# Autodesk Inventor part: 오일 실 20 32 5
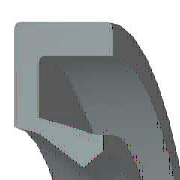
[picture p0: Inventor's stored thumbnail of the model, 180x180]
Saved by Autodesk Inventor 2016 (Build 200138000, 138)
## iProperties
IsCustomPart: 0
Created: 2012-02
Part Number: 오일 실 20 32 5
Material: 고무
Description: 오일 실 - 비스프링, 조립 GA
Document SubType Name: Modeling
Standard: JIS B 2402
Designer: mduedu
Standards Organization: JIS
Language: ko-KR
Size Designation: 20 32 5 A
Categories: <MemberInstance><Categories><Category DisplayName="샤프트 부품" InternalName="7f7aeb1f-a693-4053-b835-cee3144e0d98" Mnemonic="SHFT"><Category DisplayName="실링" Intern
Density: 0.93 g/cm^3
Appearance: Rubber-Black
Author: mduedu
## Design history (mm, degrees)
fillet "모깎기2" dims "d33" = 0.5
body "Solid1"
revolve "회전1" stored, may be unused: angle "d27" = 360 deg
fillet "모깎기1" dims "d28" = 0.25 (= 0.05 x b)
sketch "스케치2"
  geometry: L1 (11.971, -3.75)-(12.571, -5); L2 (11.171, -3.438)-(11.971, -3.75); L3 (10, -1.375)-(11.171, -3.438); L4 (10.923, -0.75)-(10, -1.375); L5 (13.6, -4.375)-(10.923, -0.75); L6 (13.6, -0.25)-(13.6, -4.375); L7 (14.8, -0.25)-(13.6, -0.25); L8 (14.8, 0)-(14.8, -0.25); L9 (16, 0)-(14.8, 0); L10 (16, -5)-(16, 0); L11 (12.571, -5)-(16, -5); L12 (0, -9.6)-(0, 1.6) reference; L13 (28, 0)-(14, 0) reference
  constraints: 22 end point, 3 horizontal, 3 vertical
  dimensions: "d2" = 5 distance of L10.start L9.start (= b); "d4" = 1.2 distance of L9.start L8.start (= 0.1 x dd - 0.1 x Diam); "d6" = 0.25 distance of L8.start L7.start (= 0.05 x b); "d8" = 0.92308 horizontal distance of L4.start L3.start (= 0.0769231 x dd - 0.0769231 x Diam); "d10" = 0.625 vertical distance of L5.start L10.start (= 0.125 x b); "d12" = 1.2 distance of L7.start L6.start (= 0.1 x dd - 0.1 x Diam); "d14" = 0.5 vertical distance of L4.start L6.start (= 0.1 x b); "d16" = 3.42857 distance of L1.end L10.start (= 0.285714 x dd - 0.285714 x Diam); "d18" = 0.6 horizontal distance of L1.start L1.end (= 0.05 x dd - 0.05 x Diam); "d20" = 0.625 vertical distance of L4.start L3.start (= 0.125 x b); "d22" = 1.25 vertical distance of L1.start L1.end (= 0.25 x b); "d24" = 0.8 horizontal distance of L2.start L1.start (= 0.0666667 x dd - 0.0666667 x Diam); "d26" = 0.3125 vertical distance of L2.start L1.start (= 0.0625 x b); "d29" = 0 distance between parallel lines of L13 L9; "d30" = 10 distance from line of L3.start L12 (= 0.5 x Diam); "d31" = 16 distance between parallel lines of L12 L10 (= 0.5 x dd)
other parameters: "dd" = 32 [user parameter; used in 7 equation terms], "b" = 5 [user parameter; used in 8 equation terms], "d1" = 8 (derived), "d3" = 2 (derived), "d5" = 0.4 (derived), "d7" = 1.53846 (derived), "d9" = 1 (derived), "d11" = 2 (derived), "d13" = 0.8 (derived), "d15" = 5.71429 (derived), "d17" = 1 (derived), "d19" = 1 (derived), "d21" = 2 (derived), "d23" = 1.33333 (derived), "d25" = 0.5 (derived), "d32" = 0
